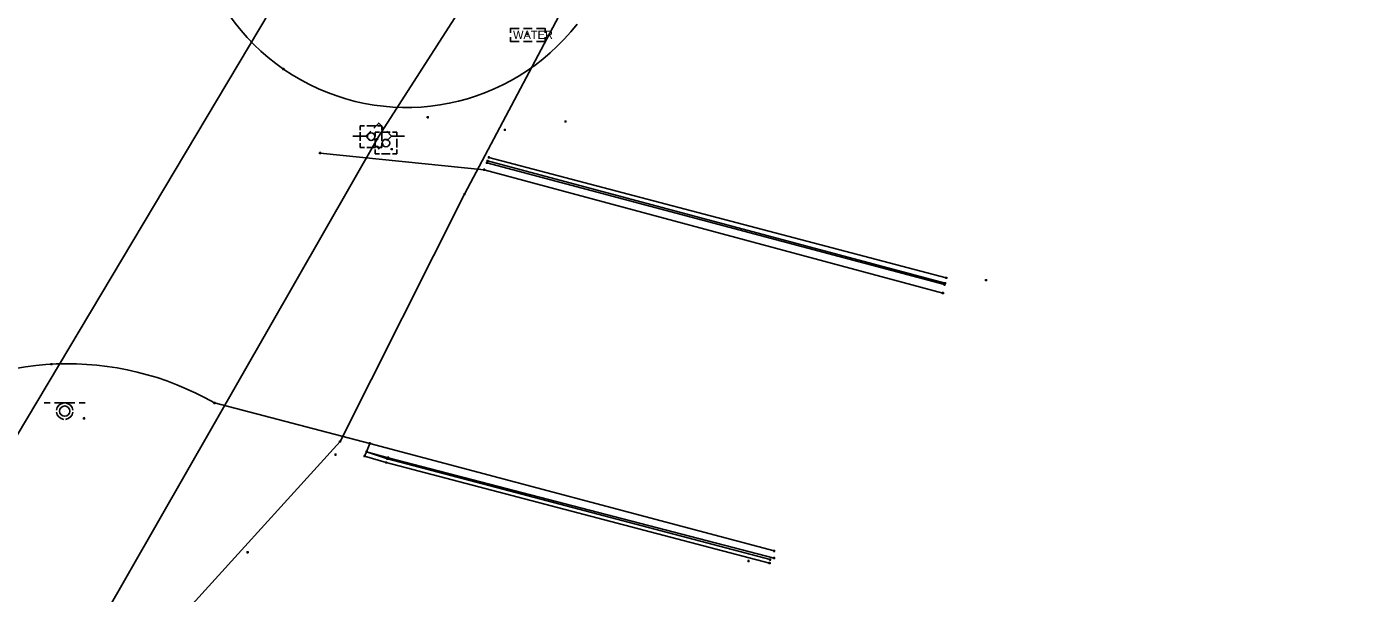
# Model space of a CAD drawing. Extents: x 1954856 to 2011933, y 399149 to 426294.
# Drawn here: x 2007162.2 to 2007316.4, y 403105.1 to 403170.4 of the extents above; entities that cross this region are included whole.
import ezdxf

# ---------------------------------------------------------------- set-up
doc = ezdxf.new("R2010")
doc.units = 0
for name, color, linetype in [('BankMent_ep', 7, 'Continuous'), ('CGBack_ep', 7, 'Continuous'), ('CGep_ep', 7, 'Continuous'), ('CGFace_ep', 7, 'Continuous'), ('ElecAer_ep', 7, 'Continuous'), ('Fence_ep', 7, 'Continuous'), ('Gates_ep', 7, 'Continuous'), ('MeterWater_ep', 7, 'Continuous'), ('PavtAsphalt_ep', 7, 'Continuous'), ('PipeCulvert_ep', 7, 'Continuous'), ('PointLocator_ep', 7, 'Continuous'), ('PoleElec_ep', 7, 'Continuous'), ('SignSingle_ep', 7, 'Continuous'), ('TelePed_ep', 7, 'Continuous')]:
    doc.layers.add(name, color=color, linetype=linetype)

msp = doc.modelspace()

# ---------------------------------------------------------------- linework, layer by layer
at = {"layer": 'BankMent_ep'}
msp.add_arc((2007205.94, 403186.01), 24.91, 159.2289, 322.1605, dxfattribs=at)
at = {"layer": 'CGBack_ep'}
for points in [[(2007215.45, 403155.35), (2007268.19, 403141.45)], [(2007247.81, 403108.54), (2007203.6, 403120.15), (2007201.12, 403120.87), (2007201.35, 403121.39)]]:
    msp.add_lwpolyline(points, dxfattribs=at)
at = {"layer": 'CGep_ep'}
for points in [[(2007215.21, 403154.72), (2007267.98, 403140.67)], [(2007248.33, 403109.12), (2007203.82, 403120.7), (2007201.35, 403121.39)]]:
    msp.add_lwpolyline(points, dxfattribs=at)
at = {"layer": 'CGFace_ep'}
for points in [[(2007215.29, 403154.93), (2007268.05, 403140.82)], [(2007247.87, 403108.94), (2007203.74, 403120.57), (2007201.35, 403121.39), (2007201.73, 403122.35)]]:
    msp.add_lwpolyline(points, dxfattribs=at)
at = {"layer": 'ElecAer_ep'}
for points in [[(2007214.12, 403175.55), (2007202.74, 403157.81)], [(2007202.74, 403157.81), (2007056.29, 402901.84), (2006961.74, 402740.31), (2007001.09, 402727.9)]]:
    msp.add_lwpolyline(points, dxfattribs=at)
at = {"layer": 'Fence_ep'}
for points in [[(2007316.39, 403230.79), (2007270.37, 403260.12), (2007212.64, 403151.1)], [(2007198.28, 403122.58), (2007178.18, 403100.42), (2007081.01, 402932.23)]]:
    msp.add_lwpolyline(points, dxfattribs=at)
at = {"layer": 'Gates_ep'}
msp.add_lwpolyline([(2007212.64, 403151.1), (2007198.28, 403122.58)], dxfattribs=at)
at = {"layer": 'MeterWater_ep'}
msp.add_line((2007219.93, 403169.48), (2007219.93, 403169.48), dxfattribs=at)
for points in [[(2007217.93, 403169.73), (2007217.93, 403170.23), (2007218.93, 403170.23)], [(2007218.93, 403168.73), (2007217.93, 403168.73), (2007217.93, 403169.23)], [(2007219.43, 403170.23), (2007220.43, 403170.23)], [(2007220.93, 403170.23), (2007221.93, 403170.23), (2007221.93, 403169.73)], [(2007221.93, 403169.23), (2007221.93, 403168.73), (2007220.93, 403168.73)], [(2007220.43, 403168.73), (2007219.43, 403168.73)]]:
    msp.add_lwpolyline(points, dxfattribs=at)
at = {"layer": 'PavtAsphalt_ep'}
for p, q in [((2007214.9, 403153.92), (2007195.98, 403155.84)), ((2007183.8, 403127.01), (2007201.73, 403122.35))]:
    msp.add_line(p, q, dxfattribs=at)
for points in [[(2007214.9, 403153.92), (2007267.81, 403139.7)], [(2007201.73, 403122.35), (2007248.34, 403109.94)]]:
    msp.add_lwpolyline(points, dxfattribs=at)
msp.add_arc((2007166.87, 403097.62), 33.92, 60.0582, 124.4338, dxfattribs=at)
at = {"layer": 'PipeCulvert_ep'}
msp.add_lwpolyline([(2007154.82, 403112.92), (2007195.09, 403180.49)], dxfattribs=at)
at = {"layer": 'PointLocator_ep'}
for p, q in [((2007220, 403169.59), (2007219.75, 403169.59)), ((2007219.87, 403169.47), (2007219.87, 403169.72)), ((2007219.87, 403169.59), (2007219.87, 403169.59)), ((2007191.86, 403165.55), (2007191.61, 403165.55)), ((2007191.73, 403165.42), (2007191.73, 403165.67)), ((2007191.73, 403165.55), (2007191.73, 403165.55)), ((2007208.52, 403159.97), (2007208.27, 403159.97)), ((2007208.39, 403159.84), (2007208.39, 403160.09)), ((2007208.39, 403159.97), (2007208.39, 403159.97)), ((2007217.41, 403158.52), (2007217.16, 403158.52)), ((2007217.29, 403158.4), (2007217.29, 403158.65)), ((2007217.29, 403158.52), (2007217.29, 403158.52)), ((2007224.4, 403159.49), (2007224.15, 403159.49)), ((2007224.27, 403159.36), (2007224.27, 403159.61)), ((2007224.27, 403159.49), (2007224.27, 403159.49)), ((2007202.67, 403157.45), (2007202.42, 403157.45)), ((2007202.54, 403157.32), (2007202.54, 403157.57)), ((2007202.54, 403157.45), (2007202.54, 403157.45)), ((2007196.1, 403155.84), (2007195.85, 403155.84)), ((2007195.98, 403155.72), (2007195.98, 403155.97)), ((2007195.98, 403155.84), (2007195.98, 403155.84)), ((2007202.73, 403156.56), (2007202.48, 403156.56)), ((2007202.6, 403156.43), (2007202.6, 403156.68)), ((2007202.6, 403156.56), (2007202.6, 403156.56)), ((2007204.37, 403156.3), (2007204.12, 403156.3)), ((2007204.25, 403156.17), (2007204.25, 403156.42)), ((2007204.25, 403156.3), (2007204.25, 403156.3)), ((2007215.57, 403155.35), (2007215.32, 403155.35)), ((2007215.45, 403155.22), (2007215.45, 403155.47)), ((2007215.45, 403155.35), (2007215.45, 403155.35)), ((2007215.02, 403153.92), (2007214.77, 403153.92)), ((2007214.9, 403153.8), (2007214.9, 403154.05)), ((2007214.9, 403153.92), (2007214.9, 403153.92)), ((2007215.33, 403154.72), (2007215.08, 403154.72)), ((2007215.41, 403154.93), (2007215.16, 403154.93)), ((2007215.21, 403154.59), (2007215.21, 403154.84)), ((2007215.21, 403154.72), (2007215.21, 403154.72)), ((2007215.29, 403154.8), (2007215.29, 403155.05)), ((2007215.29, 403154.93), (2007215.29, 403154.93)), ((2007212.76, 403151.1), (2007212.51, 403151.1)), ((2007212.64, 403150.98), (2007212.64, 403151.23)), ((2007212.64, 403151.1), (2007212.64, 403151.1)), ((2007268.32, 403141.45), (2007268.07, 403141.45)), ((2007268.19, 403141.33), (2007268.19, 403141.58)), ((2007268.19, 403141.45), (2007268.19, 403141.45)), ((2007272.77, 403141.05), (2007272.77, 403141.3)), ((2007267.81, 403139.58), (2007267.81, 403139.83)), ((2007268.1, 403140.67), (2007267.85, 403140.67)), ((2007268.18, 403140.82), (2007267.93, 403140.82)), ((2007267.98, 403140.54), (2007267.98, 403140.79)), ((2007267.98, 403140.67), (2007267.98, 403140.67)), ((2007268.05, 403140.7), (2007268.05, 403140.95)), ((2007268.05, 403140.82), (2007268.05, 403140.82)), ((2007272.9, 403141.17), (2007272.65, 403141.17)), ((2007272.77, 403141.17), (2007272.77, 403141.17)), ((2007267.93, 403139.7), (2007267.68, 403139.7)), ((2007267.81, 403139.7), (2007267.81, 403139.7)), ((2007165.12, 403131.49), (2007164.87, 403131.49)), ((2007165, 403131.36), (2007165, 403131.61)), ((2007165, 403131.49), (2007165, 403131.49)), ((2007183.92, 403127.01), (2007183.67, 403127.01)), ((2007183.8, 403126.89), (2007183.8, 403127.14)), ((2007183.8, 403127.01), (2007183.8, 403127.01)), ((2007168.89, 403125.24), (2007168.64, 403125.24)), ((2007168.77, 403125.12), (2007168.77, 403125.37)), ((2007168.77, 403125.24), (2007168.77, 403125.24)), ((2007198.41, 403122.58), (2007198.16, 403122.58)), ((2007198.28, 403122.45), (2007198.28, 403122.7)), ((2007198.28, 403122.58), (2007198.28, 403122.58)), ((2007201.48, 403121.39), (2007201.23, 403121.39)), ((2007201.35, 403121.27), (2007201.35, 403121.52)), ((2007201.35, 403121.39), (2007201.35, 403121.39)), ((2007201.86, 403122.35), (2007201.61, 403122.35)), ((2007201.73, 403122.23), (2007201.73, 403122.48)), ((2007201.73, 403122.35), (2007201.73, 403122.35)), ((2007197.89, 403121.06), (2007197.64, 403121.06)), ((2007197.77, 403120.93), (2007197.77, 403121.18)), ((2007197.77, 403121.06), (2007197.77, 403121.06)), ((2007201.25, 403120.87), (2007201, 403120.87)), ((2007201.12, 403120.75), (2007201.12, 403121)), ((2007201.12, 403120.87), (2007201.12, 403120.87)), ((2007203.73, 403120.15), (2007203.48, 403120.15)), ((2007203.6, 403120.03), (2007203.6, 403120.28)), ((2007203.6, 403120.15), (2007203.6, 403120.15)), ((2007203.87, 403120.57), (2007203.62, 403120.57)), ((2007203.95, 403120.7), (2007203.7, 403120.7)), ((2007203.74, 403120.45), (2007203.74, 403120.7)), ((2007203.74, 403120.57), (2007203.74, 403120.57)), ((2007203.82, 403120.57), (2007203.82, 403120.82)), ((2007203.82, 403120.7), (2007203.82, 403120.7)), ((2007187.75, 403109.79), (2007187.5, 403109.79)), ((2007187.62, 403109.66), (2007187.62, 403109.91)), ((2007187.62, 403109.79), (2007187.62, 403109.79)), ((2007245.39, 403108.66), (2007245.39, 403108.91)), ((2007247.99, 403108.94), (2007247.74, 403108.94)), ((2007247.87, 403108.82), (2007247.87, 403109.07)), ((2007247.87, 403108.94), (2007247.87, 403108.94)), ((2007248.45, 403109.12), (2007248.2, 403109.12)), ((2007248.46, 403109.94), (2007248.21, 403109.94)), ((2007248.33, 403109), (2007248.33, 403109.25)), ((2007248.33, 403109.12), (2007248.33, 403109.12)), ((2007248.34, 403109.82), (2007248.34, 403110.07)), ((2007248.34, 403109.94), (2007248.34, 403109.94)), ((2007245.51, 403108.78), (2007245.26, 403108.78)), ((2007245.39, 403108.78), (2007245.39, 403108.78)), ((2007247.94, 403108.54), (2007247.69, 403108.54)), ((2007247.81, 403108.42), (2007247.81, 403108.67)), ((2007247.81, 403108.54), (2007247.81, 403108.54))]:
    msp.add_line(p, q, dxfattribs=at)
at = {"layer": 'PoleElec_ep'}
for p, q in [((2007201.25, 403157.81), (2007201.82, 403158.38)), ((2007199.75, 403157.81), (2007201.25, 403157.81)), ((2007201.82, 403157.24), (2007201.25, 403157.81)), ((2007202.74, 403157.81), (2007202.74, 403157.81)), ((2007205.72, 403157.81), (2007204.22, 403157.81))]:
    msp.add_line(p, q, dxfattribs=at)
for points in [[(2007202.17, 403158.73), (2007202.74, 403159.3), (2007203.3, 403158.73)], [(2007203.66, 403158.38), (2007204.22, 403157.81), (2007203.66, 403157.24)], [(2007203.3, 403156.89), (2007202.74, 403156.32), (2007202.17, 403156.89)]]:
    msp.add_lwpolyline(points, dxfattribs=at)
at = {"layer": 'SignSingle_ep'}
for p, q in [((2007164.15, 403127.02), (2007164.85, 403127.02)), ((2007165.35, 403127.02), (2007167.7, 403127.02)), ((2007166.53, 403126.07), (2007166.53, 403126.07)), ((2007168.2, 403127.02), (2007168.9, 403127.02))]:
    msp.add_line(p, q, dxfattribs=at)
msp.add_circle((2007166.53, 403126.07), 0.594, dxfattribs=at)
for start, end in [(96.0423, 173.9577), (186.0423, 263.9577), (6.0423, 83.9577), (276.0423, 353.9577)]:
    msp.add_arc((2007166.53, 403126.07), 0.95, start, end, dxfattribs=at)
at = {"layer": 'TelePed_ep'}
for p, q in [((2007200.62, 403159), (2007201.12, 403159)), ((2007200.62, 403158.5), (2007200.62, 403159)), ((2007200.62, 403157.25), (2007200.62, 403158.25)), ((2007201.37, 403159), (2007202.37, 403159)), ((2007202.62, 403159), (2007203.12, 403159)), ((2007203.12, 403158.5), (2007203.12, 403159)), ((2007203.12, 403157.25), (2007203.12, 403158.25)), ((2007200.62, 403156.5), (2007200.62, 403157)), ((2007201.87, 403157.75), (2007201.87, 403157.75)), ((2007202.32, 403158.24), (2007202.82, 403158.24)), ((2007202.32, 403157.74), (2007202.32, 403158.24)), ((2007202.32, 403156.49), (2007202.32, 403157.49)), ((2007203.07, 403158.24), (2007204.07, 403158.24)), ((2007203.12, 403156.5), (2007203.12, 403157)), ((2007203.57, 403156.99), (2007203.57, 403156.99)), ((2007204.32, 403158.24), (2007204.82, 403158.24)), ((2007204.82, 403157.74), (2007204.82, 403158.24)), ((2007204.82, 403156.49), (2007204.82, 403157.49)), ((2007201.12, 403156.5), (2007200.62, 403156.5)), ((2007202.37, 403156.5), (2007201.37, 403156.5)), ((2007202.32, 403155.74), (2007202.32, 403156.24)), ((2007202.82, 403155.74), (2007202.32, 403155.74)), ((2007203.12, 403156.5), (2007202.62, 403156.5)), ((2007204.07, 403155.74), (2007203.07, 403155.74)), ((2007204.82, 403155.74), (2007204.32, 403155.74)), ((2007204.82, 403155.74), (2007204.82, 403156.24))]:
    msp.add_line(p, q, dxfattribs=at)
for centre in [(2007201.87, 403157.75), (2007203.57, 403156.99)]:
    msp.add_circle(centre, 0.438, dxfattribs=at)

# ---------------------------------------------------------------- texts
at = {"layer": 'MeterWater_ep'}
msp.add_text('WATER', height=0.95, dxfattribs=at).set_placement((2007218.24, 403169.01))

doc.saveas('drawing.dxf')
